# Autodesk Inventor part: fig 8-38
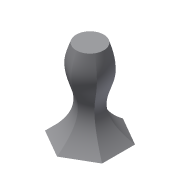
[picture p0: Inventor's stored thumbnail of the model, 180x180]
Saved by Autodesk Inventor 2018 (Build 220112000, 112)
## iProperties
Created: 2007-05
Part Number: fig 8-38
Document SubType Name: Modeling
Designer: Administrator
Density: 1 g/cm^3
Material: Generic
Appearance: Default
Author: Administrator
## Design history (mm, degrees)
sketch "Sketch1"
  geometry: L1 (0, 30)-(25.981, 15); L2 (25.981, 15)-(25.981, -15); L3 (25.981, -15)-(0, -30); L4 (0, -30)-(-25.981, -15); L5 (-25.981, -15)-(-25.981, 15); L6 (-25.981, 15)-(0, 30); 2 further points
  constraints: 12 end point, 1 coincident, 1 vertical, 14 other
workplane "Work Plane1"
sketch "Sketch2"
  geometry: C1 r 12.5 at (0, 0)
  constraints: 1 centre point, 1 other
sketch "Sketch3"
  geometry: L1 (0, 0)-(0, 75)
  constraints: 2 end point, 1 vertical, 1 other
loft "Loft1" sketch "Sketch2", "Sketch3" dims "d5" = 0, "d6" = 90 deg, "d7" = 0, "d8" = 90 deg, "d9" = 0, "d10" = 90 deg, "d11" = 0, "d12" = 0, "d13" = 233.82686, "d14" = 10, "d15" = 75, "d16" = 10, "d17" = 49.08739, "d18" = 10, "d19" = 32.19705, "d20" = 4.29294, "d21" = 35, "d22" = 2.53907, "d23" = 56.85952, "d24" = 7.58127, "d25" = 85, "d26" = 10.45619
body "Solid1"
other parameters: "d1" = 75
